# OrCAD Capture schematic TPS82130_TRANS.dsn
size Custom; title: TPS82130 17-V Input 3-A Step-Down Converter MicroSiP™; rev: 1.0; note: Datasheet: SLVSCY5D                  EVM: SLVUAK3B; note: Synchronous Step Down Converter
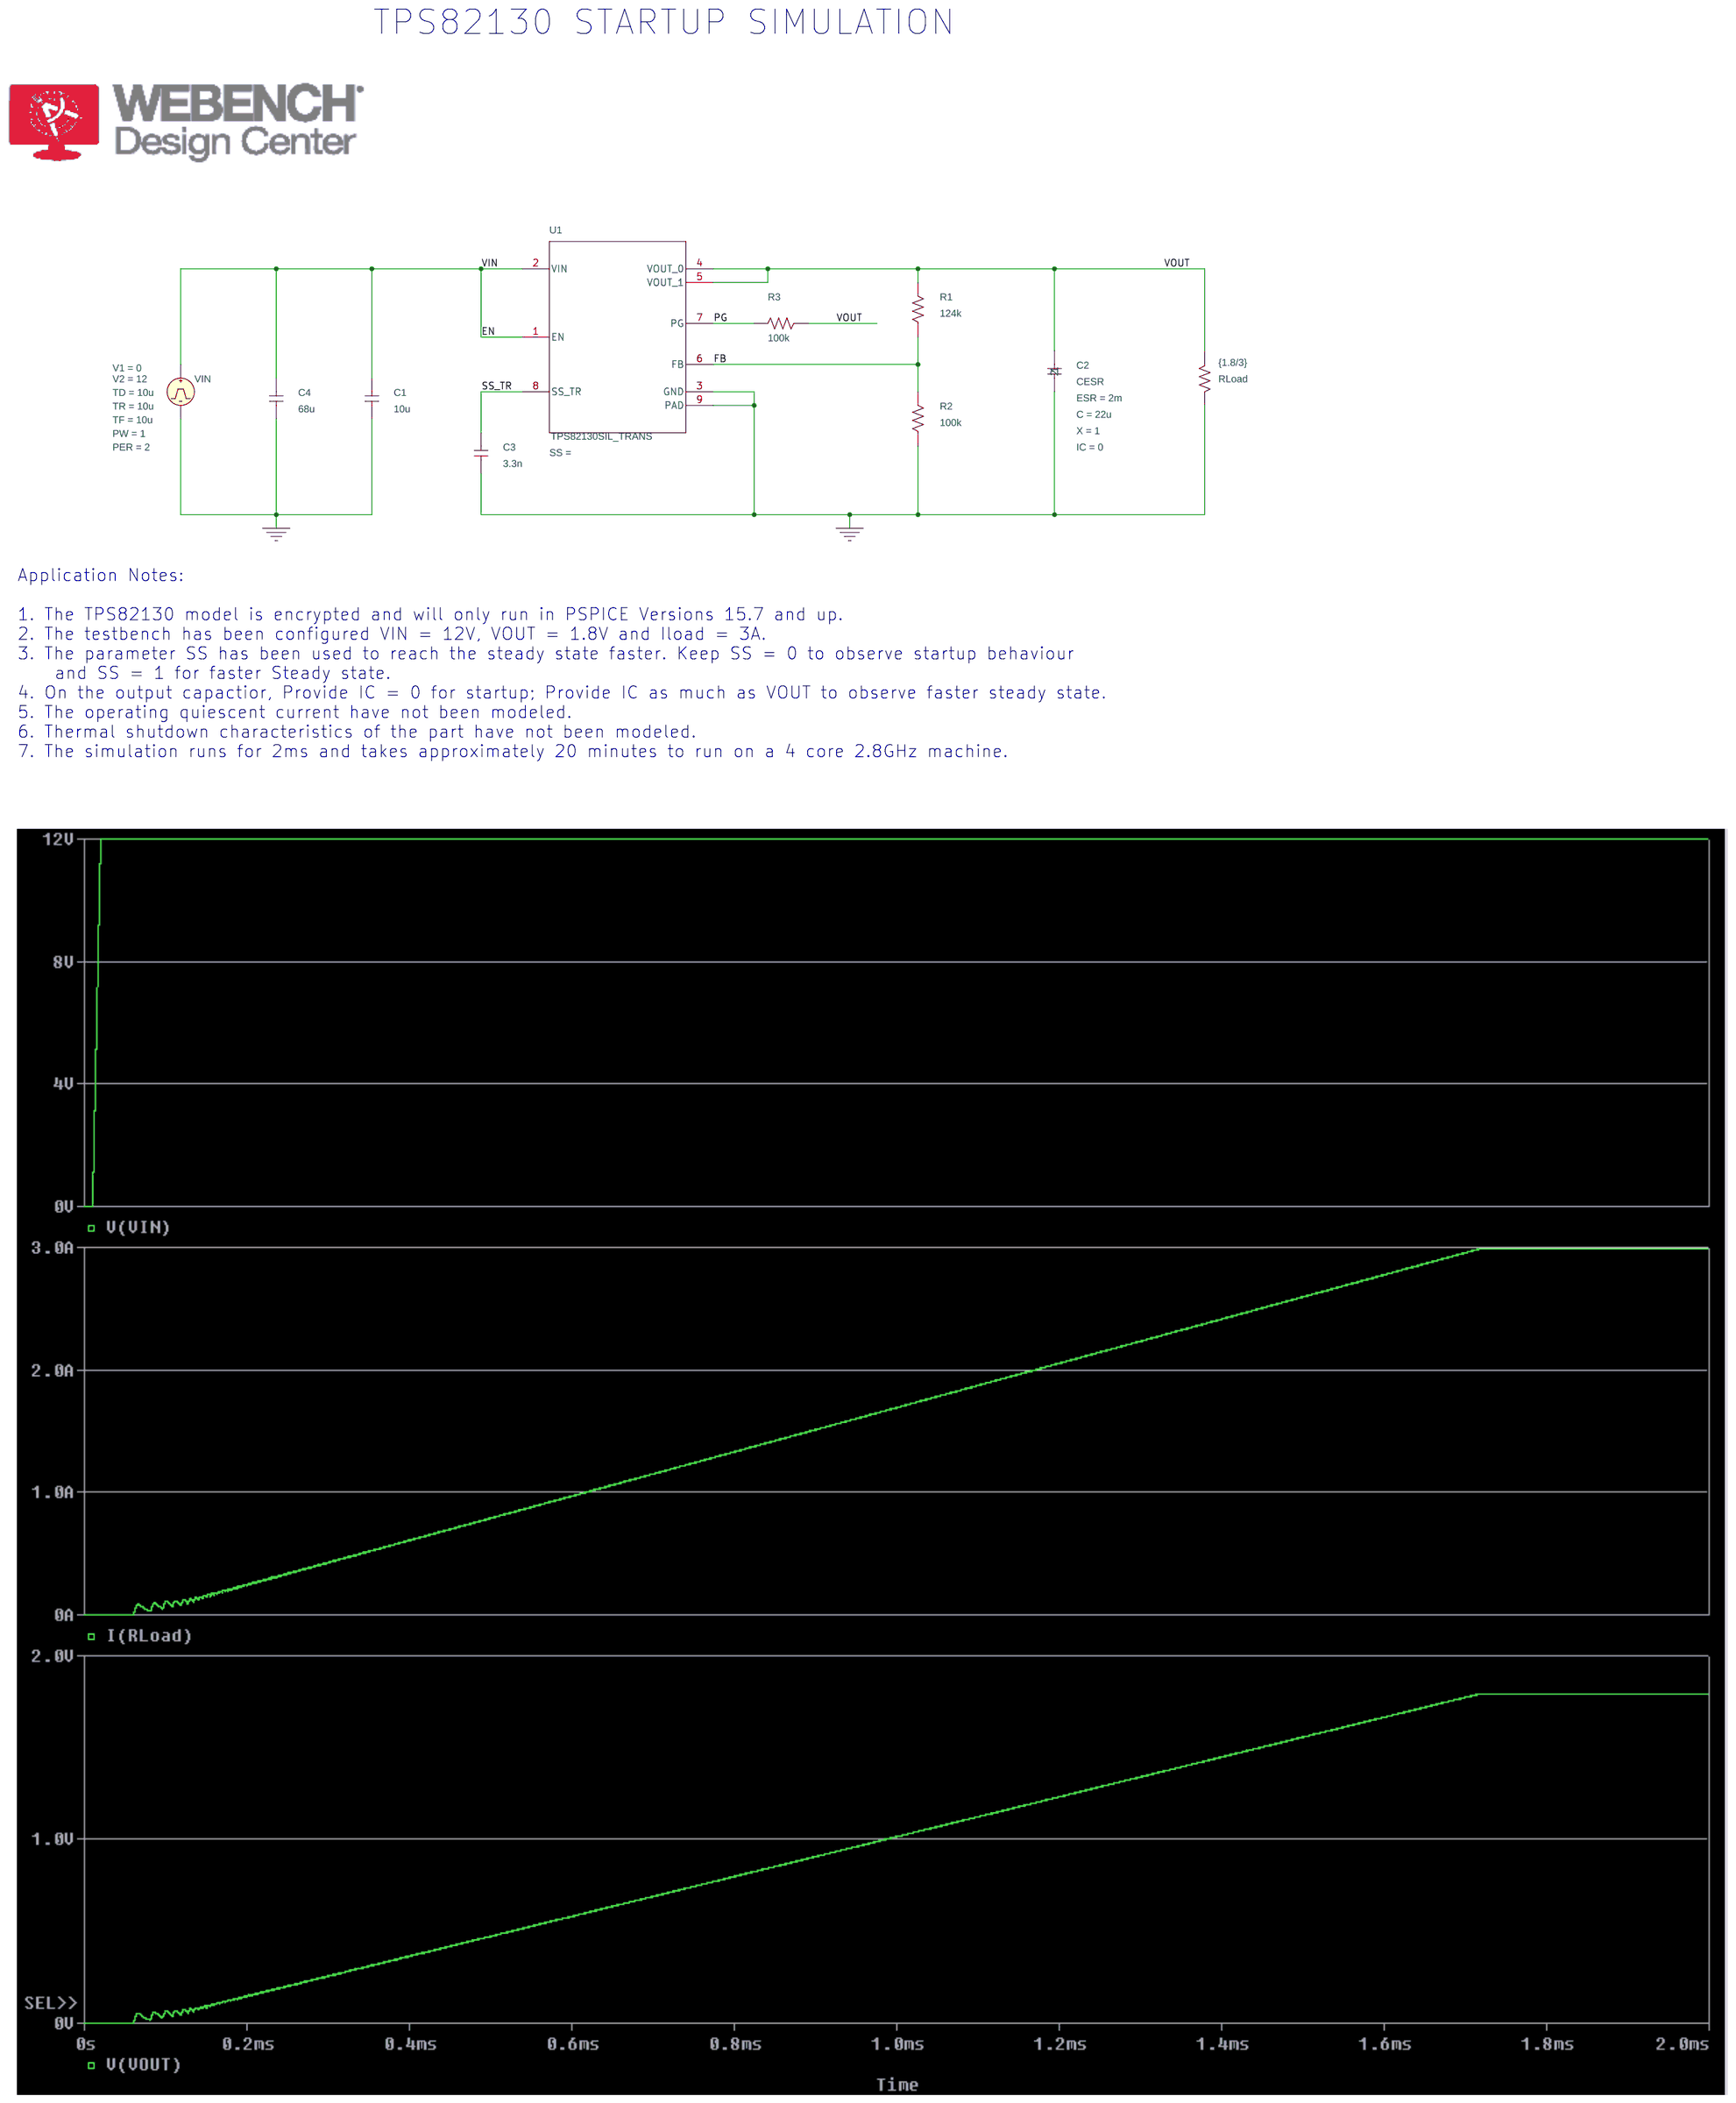
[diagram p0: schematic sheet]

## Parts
C1  10u  [RAD/CK05]
C2  CESR
C3  3.3n  [RAD/CK05]
C4  68u  [RAD/CK05]
R1  124k  [AX/RC05]
R2  100k  [AX/RC05]
R3  100k  [AX/RC05]
RLoad  {1.8/3}  [AX/RC05]
U1  TPS82130SIL_TRANS  [SIL0008D_SMD]
VIN  VPULSE

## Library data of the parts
C1 C3 C4 = C
C2 = CESR: C: 22u; ESR: 2m; IC: 0; PSpiceTemplate: X^@REFDES %1 %2 @MODEL PARAMS: ?C|C=@C||C=10U| ?ESR|ESR=@ESR||ESR=2M| ?IC|IC=@IC||IC=1N| ?X|X=@X||X=1|; X: 1
R1-R3 RLoad = R
U1 = TPS82130SIL_TRANS
VIN = VPULSE: PER: 2; PW: 1; TD: 10u; TF: 10u; TR: 10u; V1: 0; V2: 12

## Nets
0: C1.1 C2.2 C3.1 C4.1 R2.1 RLoad.2 U1.3(GND) U1.9(PAD) VIN.2(-)
EN: C1.2 C4.2 U1.1(EN) U1.2(VIN) VIN.1(+)
FB: R1.1 R2.2 U1.6(FB)
PG: R3.2 U1.7(PG)
SS_TR: C3.2 U1.8(SS_TR)
VOUT: C2.1 R1.2 R3.1 RLoad.1 U1.4(VOUT_0) U1.5(VOUT_1)

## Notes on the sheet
- TPS82130 STARTUP SIMULATION
- Application Notes:
  1. The TPS82130 model is encrypted and will only run in PSPICE Versions 15.7 and up.
  2. The testbench has been configured VIN = 12V, VOUT = 1.8V and Iload = 3A.
  3. The parameter SS has been used to reach the steady state faster. Keep SS = 0 to observe startup behaviour
      and SS = 1 for faster Steady state.
  4. On the output capactior, Provide IC = 0 for startup; Provide IC as much as VOUT to observe faster steady state.
  5. The operating quiescent current have not been modeled.
  6. Thermal shutdown characteristics of the part have not been modeled.
  7. The simulation runs for 2ms and takes approximately 20 minutes to run on a 4 core 2.8GHz machine.
